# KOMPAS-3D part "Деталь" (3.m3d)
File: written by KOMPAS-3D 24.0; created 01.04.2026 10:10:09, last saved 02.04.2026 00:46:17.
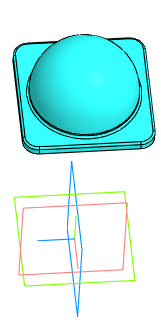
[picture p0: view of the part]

Document properties: Автор: R2D2; Полное имя файла: E:\Работа\Зайцев\Аксессуары для пневмоприводов\Блок концевых выключателей DN.ru\APL-410N EX Блок концевых выключателей DN.ru\исходные материалы\3.m3d

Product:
- Part/product: Деталь
    Масса: 0.399627

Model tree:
1. Эскиз:1
2. Элемент выдавливания:1
     Расстояние 1 = 5
3. Эскиз:2
4. Элемент выдавливания:2
     Расстояние 1 = 5
5. Уклон:1  (with: Грань.Элемент выдавливания:1)
     Угол уклона = 15
6. Уклон:3  (with: Грань.Элемент выдавливания:2)
     Угол уклона = 15
7. Массив по концентрической сетке:1  (2 pattern instances)
8. Тело 2  (2 pattern instances)
     N 1 = 1; Шаг 1 = 10; Шаг 2 = 360; Номер 1 = 1
9. Эскиз:3  (with: Грань.Элемент выдавливания:1)
10. Элемент выдавливания:3
     Расстояние 1 = 70
11. Эскиз:4  (with: Грань.Элемент выдавливания:3, Ребро.Элемент выдавливания:3)
12. Элемент выдавливания:4
     Расстояние 2 = 75
13. Эскиз:5  (with: Грань.Элемент выдавливания:3, Ребро.Элемент выдавливания:4, Ребро.Элемент выдавливания:3)
14. Скругление:1  (with: Ребро.Элемент выдавливания:3)
     Радиус = 10
15. Скругление:2  (with: Ребро.Элемент выдавливания:4)
     Радиус = 10
16. Зеркальный массив:1
17. Экземпляр ( 1 )
18. Экземпляр ( 2 )  (with: Элемент выдавливания:4, Скругление:1, Скругление:2)
19. Эскиз:6  (with: Грань.Элемент выдавливания:3, Ребро.Скругление:1, Ребро.Элемент выдавливания:3)
20. Элемент выдавливания:5
     Расстояние 2 = 20
21. Скругление:4  (with: Ребро.Элемент выдавливания:5)
     Радиус = 9
22. Скругление:6  (with: Ребро.Скругление:4, Ребро.Элемент выдавливания:5)
     Радиус = 5
23. Скругление:7  (with: Ребро.Элемент выдавливания:5)
     Радиус = 5
24. Скругление:8  (with: Ребро.Элемент выдавливания:3)
     Радиус = 10
25. Зеркальный массив:2  (with: Экземпляр ( 1 ), Экземпляр ( 2 ), Скругление:8, Элемент выдавливания:5, Скругление:7, Скругление:4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)
26. Эскиз:7  (with: Грань.Элемент выдавливания:3, Ребро.Элемент выдавливания:2)  (labels: Ребро.Тело 2.Экземпляр ( 1, 3 ))
27. Элемент выдавливания:6  (with: Грань.Элемент выдавливания:2, Массив по концентрической сетке:1, Эскиз:7, Грань.Уклон:1)  (4 pattern instances)
     Расстояние 1 = 5; N 1 = 1; Шаг 1 = 10; Шаг 2 = 360; Номер 1 = 1
28. Эскиз:8  (with: Грань.Элемент выдавливания:3, Ребро.Элемент выдавливания:3, Ребро.Элемент выдавливания:4, Ребро.Скругление:1, Ребро.Скругление:2)  (labels: Ребро.Скругление:2.Экземпляр ( 2 ); Ребро.Скругление:1.Экземпляр ( 2 ); Ребро.Элемент выдавливания:4.Экземпляр ( 2 ))
29. Элемент выдавливания:7
     Расстояние 1 = 5
30. Скругление:9  (with: Ребро.Элемент выдавливания:7)
     Радиус = 2
31. Скругление:10  (with: Грань.Элемент выдавливания:7)
     Радиус = 3
32. Скругление:11  (with: Грань.Элемент выдавливания:3)
     Радиус = 1
33. Скругление:13  (with: Грань.Элемент выдавливания:3)
     Радиус = 1
34. Эскиз:9  (with: Грань.Элемент выдавливания:1)  (labels: Ребро.Тело 2.Экземпляр ( 1, 2 ))
35. Элемент выдавливания:8
     Расстояние 2 = 10
36. Фаска:1  (with: Ребро.Элемент выдавливания:8)
     Угол = 45; Длина 1 = 1; Длина 2 = 1
37. Массив по концентрической сетке:2  (with: Элемент выдавливания:8, Эскиз:9, Фаска:1, Грань.Уклон:1)  (4 pattern instances)
     Шаг 2 = 360
38. Эскиз:10  (with: Грань.Элемент выдавливания:1)
39. Элемент выдавливания:9
     Расстояние 1 = 24
40. Эскиз:11  (with: Грань.Элемент выдавливания:9)
41. Элемент выдавливания:10
     Расстояние 1 = 3
42. Эскиз:12  (with: Грань.Элемент выдавливания:10)
43. Элемент выдавливания:11
     Расстояние 2 = 7
44. Фаска:2  (with: Ребро.Элемент выдавливания:10, Ребро.Элемент выдавливания:9)
     Угол = 45; Длина 1 = 0.5; Длина 2 = 0.5
45. Эскиз:13  (with: Грань.Элемент выдавливания:1)
46. Элемент выдавливания:12
     Расстояние 1 = 1
47. Зеркальное отражение:1  (with: Экземпляр ( 1 ), Экземпляр ( 2 ))
48. Тело 1  (with: Грань.Элемент выдавливания:3)
49. Эскиз:14  (labels: Грань.Тело 1.Экземпляр ( 2 ))
50. Элемент выдавливания:13
     Расстояние 1 = 200
51. Эскиз:15  (with: Грань.Элемент выдавливания:13, Ребро.Элемент выдавливания:13)
52. Элемент выдавливания:14
     Расстояние 1 = 8
53. Элемент выдавливания:15
     Расстояние 1 = 7
54. Элемент выдавливания:16
     Расстояние 1 = 8
55. Эскиз:16  (with: Грань.Элемент выдавливания:13)
56. Элемент выдавливания:17
     Расстояние 1 = 23
57. Скругление:14  (with: Ребро.Элемент выдавливания:17)
     Радиус = 20
58. Уклон:4  (with: Грань.Элемент выдавливания:13, Грань.Элемент выдавливания:17)
     Угол уклона = 10
59. Фаска:3  (with: Ребро.Элемент выдавливания:17)
     Угол = 45; Длина 1 = 3; Длина 2 = 3
60. Скругление:21  (with: Грань.Элемент выдавливания:14)
     Радиус = 1
61. Скругление:22  (with: Грань.Элемент выдавливания:17)
     Радиус = 3
62. Эскиз:17  (with: Грань.Элемент выдавливания:17)
63. Элемент выдавливания:18
     Расстояние 1 = 4
64. Эскиз:18
65. Элемент вращения:1
     Угол 1 = 360
66. Скругление:23  (with: Ребро.Элемент выдавливания:18)
     Радиус = 7
67. Эскиз:19  (with: Ребро.Скругление:22)
68. Элемент выдавливания:19
     Расстояние 1 = 500
69. Скругление:24  (with: Грань.Элемент выдавливания:18)
     Радиус = 1

Expressions: 148-27+15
